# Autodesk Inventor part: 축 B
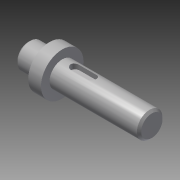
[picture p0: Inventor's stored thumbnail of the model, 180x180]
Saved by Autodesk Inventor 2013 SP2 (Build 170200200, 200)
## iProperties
Created: 2020-04
Part Number: 축 B
Material: 강철, 연강
Document SubType Name: Modeling
Designer: mduedu
Density: 7.86 g/cm^3
Mass: 57.2004 g
Surface Area: 29.0657 cm^2
Volume: 7.2774 cm^3
Author: mduedu
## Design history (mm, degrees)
revolve "회전1" stored, may be unused: angle "d11" = 90 deg
sketch "스케치3"
  geometry: L1 (0, -6)-(0, 6) reference; L2 (0, 6)-(10, 6) reference; L3 (10, 6)-(10, 10) reference; L4 (10, 10)-(16, 10) reference; L5 (16, 10)-(16, 6) reference; L6 (16, 6)-(58, 6) reference; L7 (58, 6)-(58, -6) reference; L8 (58, -6)-(16, -6) reference; L9 (16, -6)-(16, -10) reference; L10 (16, -10)-(10, -10) reference; L11 (10, -10)-(10, -6) reference; L12 (10, -6)-(0, -6) reference; L13 (20, 6)-(32, 6); L14 (32, 6)-(32, 3.5); L15 (32, 3.5)-(20, 3.5); L16 (20, 3.5)-(20, 6); 1 further point
  constraints: 8 end point, 2 parallel, 1 horizontal, 1 perpendicular, 1 point on line
  dimensions: "d17" = 12 distance of L14.end L15.end; "d18" = 2.5 distance of L13.end L14.end; "d19" = 4 distance from line of L16 L4.end
extrude "돌출2" cut sketch "스케치3" stored distance "d20" = 4; taper "d21" = 0 deg
fillet "모깎기2" dims "d22" = 2
chamfer "모따기1" distance "d23" = 1; stored, may be unused: second distance "d24" = 2, angle "d25" = 45 deg
chamfer "모따기2" distance "d26" = 1; stored, may be unused: second distance "d27" = 2, angle "d28" = 45 deg
fillet "모깎기3" dims "d29" = 0.3
node "솔리드1"
sketch "스케치1"
  geometry: L1 (0, 0)-(10, 0); L2 (10, 0)-(10, 6); L3 (10, 6)-(0, 6); L4 (0, 6)-(0, 0); L5 (10, 0)-(16, 0); L6 (16, 0)-(16, 10); L7 (16, 10)-(10, 10); L8 (10, 10)-(10, 0); L9 (16, 0)-(58, 0); L10 (58, 0)-(58, 6); L11 (58, 6)-(16, 6); L12 (16, 6)-(16, 0); L13 (58, 0)-(58, 0); L14 (58, 5)-(58, 0)
  constraints: 28 end point, 6 parallel, 4 horizontal, 3 perpendicular
  dimensions: "d2" = 10 distance of L2.end L3.end; "d3" = 6 distance of L6.end L7.end; "d7" = 12 diameter of L11 L9; "d8" = 12 diameter of L3 L1; "d9" = 20 diameter of L7 L5; "d36" = 58 distance between parallel lines of L10 L4
node "절단 모서리 투영2"
